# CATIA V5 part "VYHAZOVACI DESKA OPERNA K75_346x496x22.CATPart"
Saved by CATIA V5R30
Part number: VYHAZOVACI DESKA OPERNA
Bounding box of the stored display mesh (mm): x 0 to 22, y -150 to 150, z -173 to 173
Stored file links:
  C:\Users\ondra\Desktop\PŘÍLOHA P III\CATIA\VYHAZOVACI DESKA OPERNA K75_346x496x22.CATPart
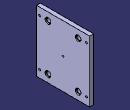
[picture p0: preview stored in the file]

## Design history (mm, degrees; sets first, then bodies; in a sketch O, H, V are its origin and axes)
Set1
  DatumSurface1 to DatumSurface42 "K75/346x"
  Plane1: type Offset, RefPlane yz-plane, Offset 22
  Point1: type OnSurface, Support DatumSurface32, Length 0, Direction edge of DatumSurface33
  Plane2: type Tangent, Support DatumSurface32, RefPoint Point1
  Plane3: type Offset, RefPlane yz-plane, Offset 3, reversed
  Join1: Elements (DatumSurface1; DatumSurface2; DatumSurface3; DatumSurface4; DatumSurface5; DatumSurface6; DatumSurface7; DatumSurface8; DatumSurface9; DatumSurface10; DatumSurface11; DatumSurface12; DatumSurface13; DatumSurface14; DatumSurface15; DatumSurface16; DatumSurface17; DatumSurface18; DatumSurface19; DatumSurface20; DatumSurface21; DatumSurface22; DatumSurface23; DatumSurface24; DatumSurface25; DatumSurface26; DatumSurface27; DatumSurface28; DatumSurface29; DatumSurface30; DatumSurface31; DatumSurface32; DatumSurface33; DatumSurface34; DatumSurface35; DatumSurface36; DatumSurface37; DatumSurface38; DatumSurface39; DatumSurface40; DatumSurface41; DatumSurface42)
Body1 (main body)
  CloseSurface1: CloseElement Join1
  Sketch1 on yz-plane, origin (0, 0, 0), H (0, 1, 0), V (0, 0, 1)
    point P1 (85, -130)
    point P2 (85, 130)
    point P3 (-85, -130)
    point P4 (-85, 130)
    distance H P1 = 130
    distance V P1 = 85
    symmetry: P1 P2 H, P1 P3 V, P2 P4 V
  Sketch2 on {plane type Tangent, Support face of CloseSurface1, RefPoint Sketch1.P3}, origin (0, -85, -130), H (0, 1, 0), V (0, 0, -1)
    point P1 (0, 0)
    reference projected point E1 (0, 0) from Sketch1.P3
    coincidence: E1 P1
  Hole1: placed by Sketch2, at (22, -85, -130) direction (-1, 0, 0), diameter 26, through (limit type 6), counterbore diameter 32, counterbore depth 6.3
  UserPattern1: of Hole1, copies 4, at the points of Sketch1
  DatumPoint1
  Plane4: type Offset, RefPlane yz-plane, Offset 39, reversed
  Sketch3 on {plane type Tangent, Support face of CloseSurface1, RefPoint vertex of DatumPoint1}, origin (-47, 0, 0), H (0, 1, 0), V (0, 0, 1)
    point P1 (0, 0)
    reference projected point E1 (0, 0) from vertex of DatumPoint1
    coincidence: E1 P1
  Hole2: placed by Sketch3, at (0, 0, 0) direction (1, 0, 0), diameter 10.106, through (limit type 6), counterbore diameter 20, counterbore depth 5, threaded "M12", thread diameter 12, thread depth 15, pitch 1.75
  Plane5: type Offset, RefPlane yz-plane, Offset 35, reversed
